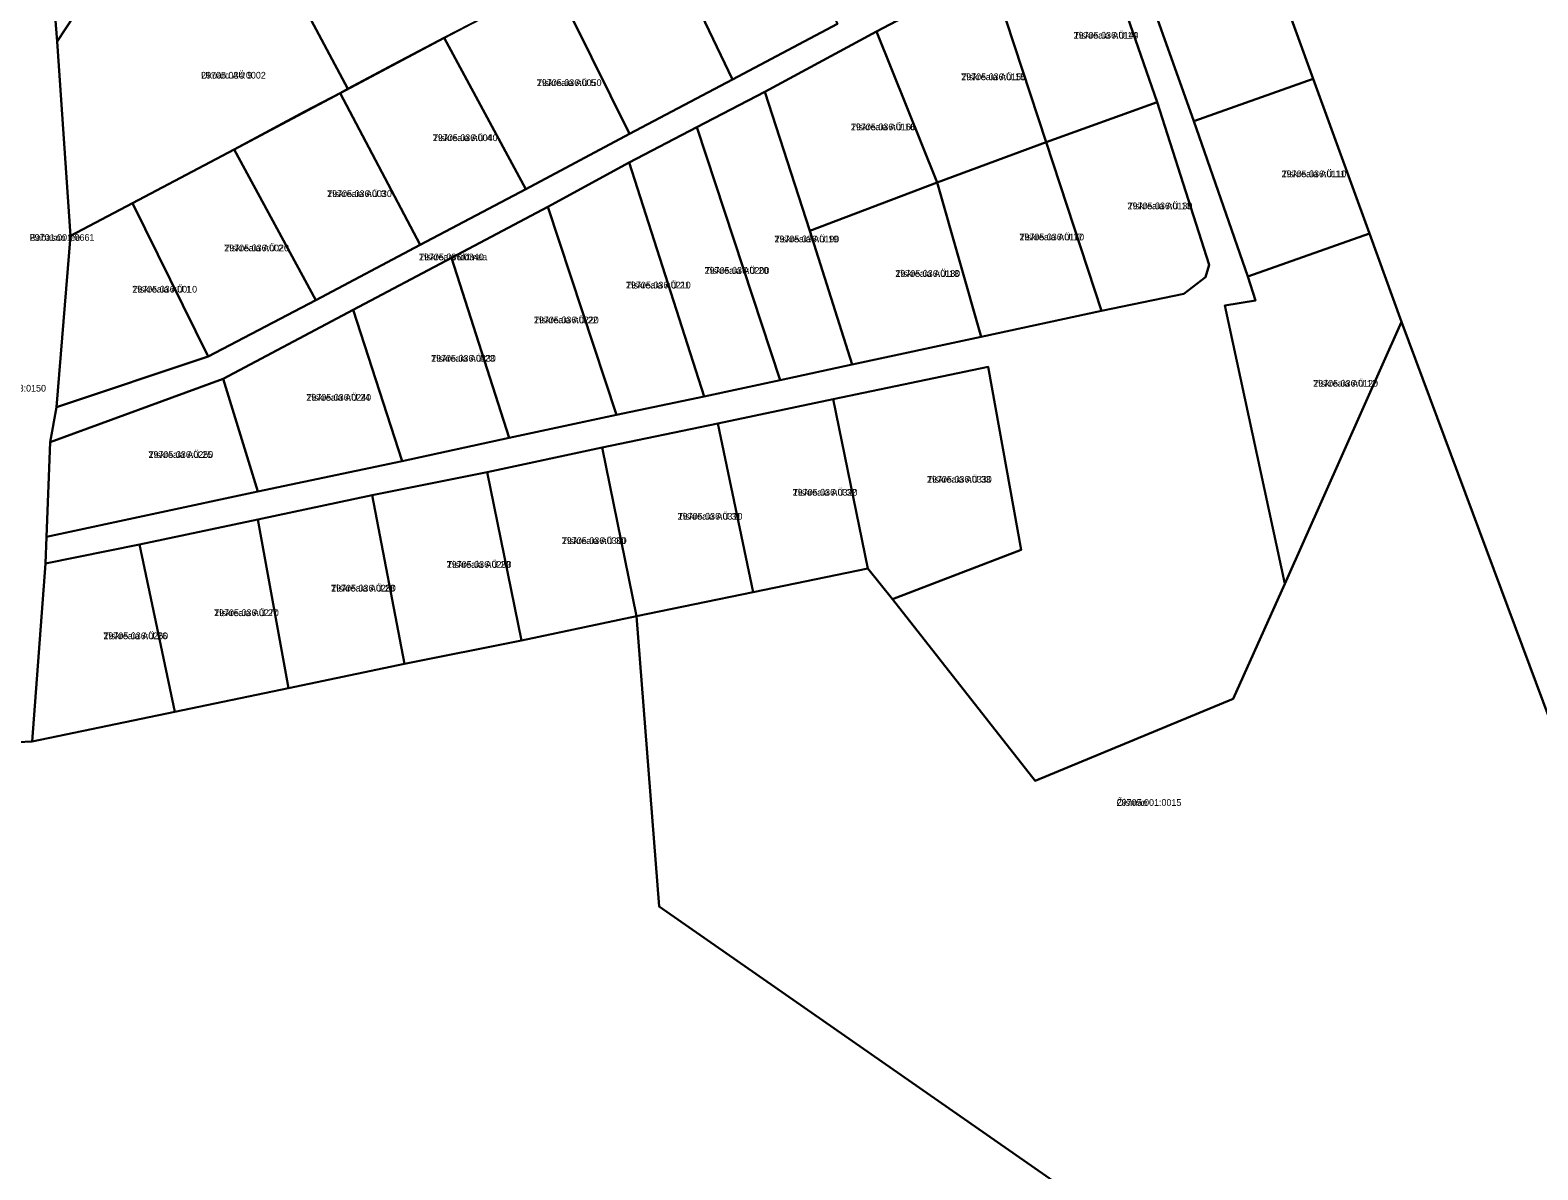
# Model space of a CAD drawing. Extents: x 504287 to 537970, y 6539941 to 6586214.
# Drawn here: x 520266.8 to 520604.6, y 6563342.8 to 6563598.1 of the extents above; entities that cross this region are included whole.
import ezdxf

# ---------------------------------------------------------------- set-up
doc = ezdxf.new("R2010")
doc.units = 0
for name, color, linetype in [('L_AADRESS', 7, 'Continuous'), ('PIIR', 7, 'Continuous'), ('TUNNUS', 7, 'Continuous')]:
    doc.layers.add(name, color=color, linetype=linetype)

msp = doc.modelspace()

# ---------------------------------------------------------------- linework, layer by layer
at = {"layer": 'PIIR'}
for points in [[(520653.9, 6563584.36), (520690.46, 6563500.96), (520766.28, 6563326.22), (520851.17, 6563135.12), (520568.37, 6562931.82), (520394.16, 6563025.62), (520531.01, 6563315.92), (520645.56, 6563341.08), (520574.09, 6563532.77), (520566.89, 6563552.57), (520554.29, 6563587.26), (520543.59, 6563616.74), (520548.53, 6563618.45), (520591.62, 6563633.38), (520591.58, 6563668.72), (520591.58, 6563670.54), (520591.55, 6563692.35), (520591.52, 6563726.22)], [(520257.63, 6563657.58), (520268.08, 6563663.97), (520271.83, 6563608.74), (520272.89, 6563595.6), (520275.86, 6563552.04), (520272.71, 6563513.64), (520271.28, 6563505.8), (520270.5, 6563484.59), (520270.25, 6563478.62), (520267.25, 6563438.79), (520257.56, 6563438.3), (520260.71, 6563484.77), (520260.51, 6563490.03), (520264.57, 6563548.68)], [(520317.96, 6563622.56), (520328.35, 6563628.05), (520348.07, 6563638.59), (520368.18, 6563600.83), (520359.58, 6563596.39), (520348.38, 6563590.49), (520337.98, 6563585.01)], [(520407.56, 6563621.77), (520429.98, 6563633.73), (520447.71, 6563599.57), (520424.16, 6563587.06)], [(520272.89, 6563595.6), (520276.58, 6563601.31), (520280.04, 6563601.69), (520283.6, 6563603.02), (520287.14, 6563604.95), (520287.05, 6563605.99), (520308.44, 6563617.53), (520317.96, 6563622.56), (520337.98, 6563585.01), (520336.23, 6563584.04), (520328.37, 6563579.95), (520312.52, 6563571.44), (520289.75, 6563559.38), (520275.86, 6563552.04)], [(520384.1, 6563609.36), (520407.56, 6563621.77), (520424.16, 6563587.06), (520401.09, 6563574.94)], [(520481.92, 6563611.29), (520493.65, 6563617.6), (520507.25, 6563616.89), (520519.29, 6563581.98), (520494.41, 6563573.02)], [(520513.26, 6563617.87), (520529.78, 6563617.25), (520543.59, 6563616.74), (520554.29, 6563587.26), (520527.51, 6563577.77)], [(520456.44, 6563597.87), (520481.92, 6563611.29), (520494.41, 6563573.02), (520470.02, 6563564.01)], [(520359.58, 6563596.39), (520384.1, 6563609.36), (520401.09, 6563574.94), (520377.85, 6563562.55)], [(520431.39, 6563584.35), (520456.44, 6563597.87), (520470.02, 6563564.01), (520441.48, 6563553.15)], [(520336.23, 6563584.04), (520359.58, 6563596.39), (520377.85, 6563562.55), (520354.18, 6563550.03)], [(520431.39, 6563584.35), (520441.48, 6563553.15), (520451.01, 6563523.21), (520434.86, 6563519.7), (520416.14, 6563576.44)], [(520527.51, 6563577.77), (520554.29, 6563587.26), (520566.89, 6563552.57), (520539.61, 6563542.98)], [(520312.52, 6563571.44), (520336.23, 6563584.04), (520354.18, 6563550.03), (520330.85, 6563537.66)], [(520494.41, 6563573.02), (520519.29, 6563581.98), (520530.98, 6563545.53), (520530.16, 6563542.81), (520525.29, 6563539.06), (520506.87, 6563535.23)], [(520416.14, 6563576.44), (520434.86, 6563519.7), (520417.84, 6563516.06), (520400.99, 6563568.53)], [(520289.75, 6563559.38), (520312.52, 6563571.44), (520330.85, 6563537.66), (520306.68, 6563525.04)], [(520470.02, 6563564.01), (520494.41, 6563573.02), (520506.87, 6563535.23), (520479.85, 6563529.45)], [(520382.77, 6563558.54), (520400.99, 6563568.53), (520417.84, 6563516.06), (520398.18, 6563511.95)], [(520441.48, 6563553.15), (520470.02, 6563564.01), (520479.85, 6563529.45), (520451.01, 6563523.21)], [(520275.86, 6563552.04), (520289.75, 6563559.38), (520306.68, 6563525.04), (520272.71, 6563513.64)], [(520361.2, 6563547.12), (520382.77, 6563558.54), (520398.18, 6563511.95), (520374.1, 6563506.84)], [(520574.09, 6563532.77), (520547.88, 6563474.07), (520534.46, 6563536.48), (520541.37, 6563537.56), (520539.61, 6563542.98), (520566.89, 6563552.57)], [(520339.18, 6563535.46), (520361.2, 6563547.12), (520374.1, 6563506.84), (520350.16, 6563501.59)], [(520310.09, 6563520.03), (520339.18, 6563535.46), (520350.16, 6563501.59), (520317.8, 6563494.75)], [(520574.09, 6563532.77), (520645.56, 6563341.08), (520531.01, 6563315.92), (520407.72, 6563401.78), (520402.68, 6563466.86), (520428.81, 6563472.26), (520454.46, 6563477.55), (520459.99, 6563470.66), (520491.97, 6563429.98), (520536.36, 6563448.34), (520547.88, 6563474.07)], [(520271.28, 6563505.8), (520310.09, 6563520.03), (520317.8, 6563494.75), (520270.5, 6563484.59)], [(520454.46, 6563477.55), (520446.69, 6563515.49), (520481.46, 6563522.74), (520488.82, 6563481.68), (520459.99, 6563470.66)], [(520420.85, 6563510.05), (520446.69, 6563515.49), (520454.46, 6563477.55), (520428.81, 6563472.26)], [(520394.97, 6563504.64), (520420.85, 6563510.05), (520428.81, 6563472.26), (520402.68, 6563466.86)], [(520369.22, 6563499.09), (520394.97, 6563504.64), (520402.68, 6563466.86), (520376.87, 6563461.42)], [(520343.43, 6563493.98), (520369.22, 6563499.09), (520376.87, 6563461.42), (520350.66, 6563456.15)], [(520317.8, 6563488.54), (520343.43, 6563493.98), (520350.66, 6563456.15), (520324.72, 6563450.71)], [(520291.32, 6563482.93), (520317.8, 6563488.54), (520324.72, 6563450.71), (520299.19, 6563445.43)], [(520270.25, 6563478.62), (520291.32, 6563482.93), (520299.19, 6563445.43), (520267.25, 6563438.79)]]:
    msp.add_lwpolyline(points, close=True, dxfattribs=at)
for points in [[(520513.26, 6563617.87), (520527.51, 6563577.77), (520539.61, 6563542.98), (520541.37, 6563537.56), (520534.46, 6563536.48), (520547.88, 6563474.07), (520536.36, 6563448.34), (520491.97, 6563429.98), (520459.99, 6563470.66), (520488.82, 6563481.68), (520481.46, 6563522.74), (520446.69, 6563515.49), (520420.85, 6563510.05), (520394.97, 6563504.64), (520369.22, 6563499.09), (520343.43, 6563493.98), (520317.8, 6563488.54), (520291.32, 6563482.93), (520270.25, 6563478.62), (520270.5, 6563484.59), (520317.8, 6563494.75), (520350.16, 6563501.59), (520374.1, 6563506.84), (520398.18, 6563511.95), (520417.84, 6563516.06), (520434.86, 6563519.7), (520451.01, 6563523.21), (520479.85, 6563529.45), (520506.87, 6563535.23), (520525.29, 6563539.06), (520530.16, 6563542.81), (520530.98, 6563545.53), (520519.29, 6563581.98), (520507.25, 6563616.89)], [(520481.92, 6563611.29), (520456.44, 6563597.87), (520431.39, 6563584.35), (520416.14, 6563576.44), (520400.99, 6563568.53), (520382.77, 6563558.54), (520361.2, 6563547.12), (520339.18, 6563535.46), (520310.09, 6563520.03), (520271.28, 6563505.8), (520272.71, 6563513.64), (520306.68, 6563525.04), (520330.85, 6563537.66), (520354.18, 6563550.03), (520377.85, 6563562.55), (520401.09, 6563574.94), (520424.16, 6563587.06), (520447.71, 6563599.57)], [(520276.58, 6563601.31), (520272.89, 6563595.6), (520271.83, 6563608.74)], [(520257.56, 6563438.3), (520267.25, 6563438.79), (520299.19, 6563445.43), (520324.72, 6563450.71), (520350.66, 6563456.15), (520376.87, 6563461.42), (520402.68, 6563466.86), (520407.72, 6563401.78), (520531.01, 6563315.92)]]:
    msp.add_lwpolyline(points, dxfattribs=at)

# ---------------------------------------------------------------- texts
at = {"layer": 'L_AADRESS'}
for s, p in [('Tiskreaia AÜ 14', (520500.61, 6563596.24)), ('Ukuaru AÜ 9', (520305.11, 6563587.3)), ('Tiskreaia AÜ 15', (520475.42, 6563586.94)), ('Tiskreaia AÜ 5', (520380.34, 6563585.62)), ('Tiskreaia AÜ 16', (520450.71, 6563575.72)), ('Tiskreaia AÜ 4', (520357.04, 6563573.29)), ('Tiskreaia AÜ 11', (520547.2, 6563565.2)), ('Tiskreaia AÜ 3', (520333.35, 6563560.75)), ('Tiskreaia AÜ 13', (520512.69, 6563558.02)), ('Rabasoo tee', (520266.71, 6563550.95)), ('Tiskreaia AÜ 2', (520310.3, 6563548.6)), ('Tiskreaia AÜ 19', (520433.57, 6563550.59)), ('Tiskreaia AÜ 17', (520488.45, 6563551.05)), ('Tiskreaia üldmaa', (520353.93, 6563546.58)), ('Tiskreaia AÜ 20', (520417.93, 6563543.55)), ('Tiskreaia AÜ 18', (520460.66, 6563542.87)), ('Tiskreaia AÜ 1', (520289.7, 6563539.35)), ('Tiskreaia AÜ 21', (520400.31, 6563540.27)), ('Tiskreaia AÜ 22', (520379.69, 6563532.47)), ('Tiskreaia AÜ 23', (520356.64, 6563523.86)), ('Tiskreaia AÜ 12', (520554.28, 6563518.26)), ('Tiskreaia AÜ 24', (520328.69, 6563515.11)), ('Tiskreaia AÜ 25', (520293.32, 6563502.31)), ('Tiskreaia AÜ 33', (520467.75, 6563496.76)), ('Tiskreaia AÜ 32', (520437.66, 6563493.84)), ('Tiskreaia AÜ 31', (520411.89, 6563488.47)), ('Tiskreaia AÜ 30', (520385.95, 6563483.01)), ('Tiskreaia AÜ 29', (520360.15, 6563477.68)), ('Tiskreaia AÜ 28', (520334.23, 6563472.37)), ('Tiskreaia AÜ 27', (520308.02, 6563466.86)), ('Tiskreaia AÜ 26', (520283.22, 6563461.69)), ('Õismäe', (520510.24, 6563424.35))]:
    msp.add_text(s, height=1.5, dxfattribs=at).set_placement(p)
at = {"layer": 'TUNNUS'}
for s, p in [('29705:036:0140', (520500.61, 6563596.24)), ('29705:034:0002', (520305.11, 6563587.3)), ('29705:036:0150', (520475.42, 6563586.94)), ('29705:036:0050', (520380.34, 6563585.62)), ('29705:036:0040', (520357.04, 6563573.29)), ('29705:036:0160', (520450.71, 6563575.72)), ('29705:036:0110', (520547.2, 6563565.2)), ('29705:036:0030', (520333.35, 6563560.75)), ('29705:036:0130', (520512.69, 6563558.02)), ('29701:001:0661', (520266.71, 6563550.95)), ('29705:036:0190', (520433.57, 6563550.59)), ('29705:036:0170', (520488.45, 6563551.05)), ('29705:036:0020', (520310.3, 6563548.6)), ('29705:036:0340', (520353.93, 6563546.58)), ('29705:036:0200', (520417.93, 6563543.55)), ('29705:036:0180', (520460.66, 6563542.87)), ('29705:036:0010', (520289.7, 6563539.35)), ('29705:036:0210', (520400.31, 6563540.27)), ('29705:036:0220', (520379.69, 6563532.47)), ('29705:036:0230', (520356.64, 6563523.86)), ('29705:033:0150', (520255.86, 6563517.17)), ('29705:036:0240', (520328.69, 6563515.11)), ('29705:036:0120', (520554.28, 6563518.26)), ('29705:036:0250', (520293.32, 6563502.31)), ('29705:036:0330', (520467.75, 6563496.76)), ('29705:036:0320', (520437.66, 6563493.84)), ('29705:036:0310', (520411.89, 6563488.47)), ('29705:036:0300', (520385.95, 6563483.01)), ('29705:036:0290', (520360.15, 6563477.68)), ('29705:036:0280', (520334.23, 6563472.37)), ('29705:036:0270', (520308.02, 6563466.86)), ('29705:036:0260', (520283.22, 6563461.69)), ('29705:001:0015', (520510.24, 6563424.35))]:
    msp.add_text(s, height=1.5, dxfattribs=at).set_placement(p)

doc.saveas('drawing.dxf')
